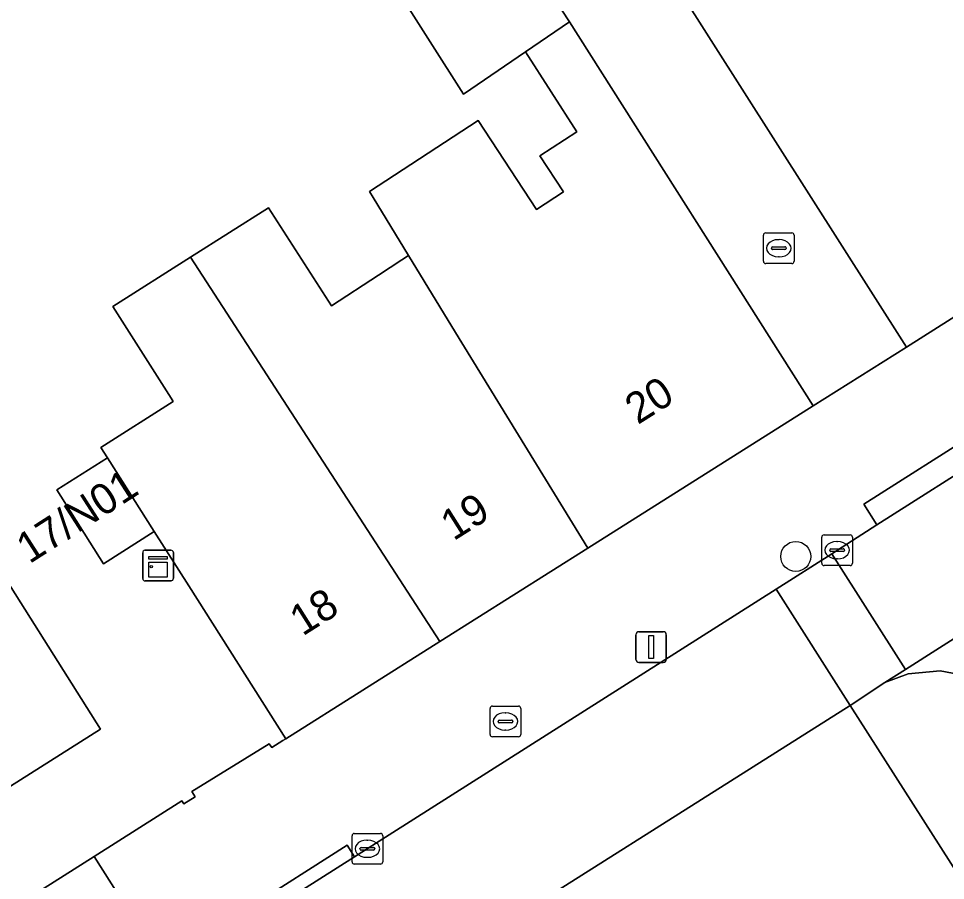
# Model space of a CAD drawing. Extents: x 160663 to 161506, y 382245 to 383291.
# Drawn here: x 160785.26 to 160815.49, y 383191.57 to 383219.69 of the extents above; entities that cross this region are included whole.
import ezdxf

# ---------------------------------------------------------------- set-up
doc = ezdxf.new("R2010")
doc.units = 0
for name, color, linetype in [('IMGEO_Boom', 7, 'Continuous'), ('IMGEO_Erf', 7, 'Continuous'), ('IMGEO_Kast', 7, 'Continuous'), ('IMGEO_Kolk', 7, 'Continuous'), ('IMGEO_Lichtmast', 7, 'Continuous'), ('IMGEO_Pand', 7, 'Continuous'), ('IMGEO_Pand_nummerreeks', 7, 'Continuous'), ('IMGEO_Parkeervlak_gesloten', 7, 'Continuous'), ('IMGEO_Parkeervlak_open', 7, 'Continuous'), ('IMGEO_Rijbaan_lokaal_gesloten', 7, 'Continuous'), ('IMGEO_Rijbaan_lokaal_open', 7, 'Continuous'), ('IMGEO_Rioolput', 7, 'Continuous'), ('IMGEO_Voetgangersgebied_open', 7, 'Continuous'), ('IMGEO_Voetpad_open', 7, 'Continuous')]:
    doc.layers.add(name, color=color, linetype=linetype)

msp = doc.modelspace()

# ---------------------------------------------------------------- linework, layer by layer
at = {"layer": 'IMGEO_Boom'}
msp.add_circle((160810.605, 383202.143), 0.489, dxfattribs=at)
at = {"layer": 'IMGEO_Erf'}
for points in [[(160799.08, 383225.923), (160803.23, 383219.586), (160811.173, 383207.059), (160814.215, 383208.968), (160806.764, 383220.698)], [(160790.812, 383201.181), (160789.687, 383202.954), (160788.036, 383201.906), (160786.509, 383204.312), (160788.159, 383205.36), (160787.946, 383205.695), (160790.307, 383207.2), (160790.242, 383207.302), (160788.34, 383210.3), (160790.873, 383211.908), (160793.413, 383213.52), (160795.464, 383210.321), (160796.995, 383211.321), (160797.758, 383211.82), (160797.977, 383211.963), (160796.829, 383213.85), (160796.707, 383214.052), (160800.251, 383216.368), (160802.147, 383213.465), (160803.027, 383214.04), (160802.265, 383215.208), (160803.466, 383215.992), (160801.794, 383218.605), (160799.769, 383217.222), (160795.199, 383224.421)], [(160781.782, 383206.257), (160787.928, 383196.514), (160781.611, 383192.511)], [(160772.211, 383182.539), (160787.728, 383192.359), (160790.588, 383194.169), (160790.653, 383194.068), (160791.019, 383194.303), (160790.91, 383194.473), (160793.433, 383196.036), (160793.515, 383195.909), (160793.875, 383196.14), (160793.972, 383196.198), (160790.812, 383201.181)]]:
    msp.add_lwpolyline(points, dxfattribs=at)
at = {"layer": 'IMGEO_Kast'}
for p, q in [((160789.309, 383201.422), (160789.309, 383202.263)), ((160789.309, 383202.263), (160789.309, 383201.422)), ((160789.384, 383202.347), (160790.225, 383202.347)), ((160790.225, 383202.347), (160789.384, 383202.347)), ((160790.309, 383202.272), (160790.309, 383201.431)), ((160790.309, 383201.431), (160790.309, 383202.272)), ((160790.234, 383201.347), (160789.393, 383201.347)), ((160789.393, 383201.347), (160790.234, 383201.347))]:
    msp.add_line(p, q, dxfattribs=at)
for points in [[(160789.504, 383202.137), (160790.104, 383202.137), (160790.104, 383202.052), (160789.504, 383202.052), (160789.504, 383202.137)], [(160789.504, 383201.962), (160790.104, 383201.962), (160790.104, 383201.473), (160789.504, 383201.473), (160789.504, 383201.962)]]:
    msp.add_lwpolyline(points, dxfattribs=at)
msp.add_circle((160789.588, 383201.811), 0.0377, dxfattribs=at)
for centre, start, end in [((160789.387, 383202.269), 92.4484, 184.2845), ((160789.387, 383202.269), 92.4484, 184.2845), ((160790.231, 383202.269), 2.4484, 94.2845), ((160790.231, 383202.269), 2.4484, 94.2845), ((160789.387, 383201.425), 182.4484, 274.2845), ((160789.387, 383201.425), 182.4484, 274.2845), ((160790.231, 383201.425), 272.4484, 4.2845), ((160790.231, 383201.425), 272.4484, 4.2845)]:
    msp.add_arc(centre, 0.0779, start, end, dxfattribs=at)
at = {"layer": 'IMGEO_Kolk'}
for p, q in [((160809.627, 383212.698), (160810.479, 383212.698)), ((160809.552, 383211.772), (160809.552, 383212.624)), ((160810.04, 383212.478), (160810.065, 383212.478)), ((160810.553, 383212.624), (160810.553, 383211.772)), ((160809.811, 383212.192), (160809.811, 383212.204)), ((160810.249, 383212.155), (160809.851, 383212.155)), ((160809.854, 383212.241), (160810.252, 383212.241)), ((160810.295, 383212.204), (160810.295, 383212.192)), ((160810.063, 383211.918), (160810.038, 383211.918)), ((160810.479, 383211.698), (160809.627, 383211.698)), ((160811.453, 383201.921), (160811.453, 383202.773)), ((160811.528, 383202.847), (160812.38, 383202.847)), ((160812.454, 383202.773), (160812.454, 383201.921)), ((160811.755, 383202.39), (160812.153, 383202.39)), ((160811.941, 383202.627), (160811.966, 383202.627)), ((160811.712, 383202.341), (160811.712, 383202.353)), ((160812.15, 383202.304), (160811.752, 383202.304)), ((160811.964, 383202.067), (160811.939, 383202.067)), ((160812.196, 383202.353), (160812.196, 383202.341)), ((160812.38, 383201.847), (160811.528, 383201.847)), ((160796.135, 383192.182), (160796.135, 383193.034)), ((160796.21, 383193.108), (160797.062, 383193.108)), ((160797.136, 383193.034), (160797.136, 383192.182)), ((160796.623, 383192.888), (160796.648, 383192.888)), ((160796.394, 383192.602), (160796.394, 383192.614)), ((160796.832, 383192.565), (160796.434, 383192.565)), ((160796.437, 383192.651), (160796.835, 383192.651)), ((160796.878, 383192.614), (160796.878, 383192.602)), ((160797.062, 383192.108), (160796.21, 383192.108)), ((160796.646, 383192.328), (160796.621, 383192.328))]:
    msp.add_line(p, q, dxfattribs=at)
for points in [[(160809.627, 383212.698), (160810.479, 383212.698)], [(160809.552, 383211.772), (160809.552, 383212.624)], [(160810.553, 383212.624), (160810.553, 383211.772)], [(160810.479, 383211.698), (160809.627, 383211.698)], [(160811.453, 383201.921), (160811.453, 383202.773)], [(160811.528, 383202.847), (160812.38, 383202.847)], [(160812.454, 383202.773), (160812.454, 383201.921)], [(160812.38, 383201.847), (160811.528, 383201.847)], [(160796.135, 383192.182), (160796.135, 383193.034)], [(160796.21, 383193.108), (160797.062, 383193.108)], [(160797.136, 383193.034), (160797.136, 383192.182)], [(160797.062, 383192.108), (160796.21, 383192.108)]]:
    msp.add_lwpolyline(points, dxfattribs=at)
for centre, radius, start, end in [((160809.629, 383212.622), 0.0765, 91.552, 178.448), ((160809.629, 383212.622), 0.0765, 91.552, 178.448), ((160810.477, 383212.622), 0.0765, 1.552, 88.448), ((160810.477, 383212.622), 0.0765, 1.552, 88.448), ((160809.851, 383212.201), 0.0403, 85.8775, 175.7526), ((160809.848, 383212.191), 0.0366, 178.938, 274.7102), ((160810.252, 383212.198), 0.043, 264.8664, 352.4533), ((160810.256, 383212.203), 0.0386, 1.7309, 96.639), ((160809.629, 383211.774), 0.0765, 181.552, 268.448), ((160809.629, 383211.774), 0.0765, 181.552, 268.448), ((160810.477, 383211.774), 0.0765, 271.552, 358.448), ((160810.477, 383211.774), 0.0765, 271.552, 358.448), ((160811.53, 383202.771), 0.0765, 91.552, 178.448), ((160811.53, 383202.771), 0.0765, 91.552, 178.448), ((160812.378, 383202.771), 0.0765, 1.552, 88.448), ((160812.378, 383202.771), 0.0765, 1.552, 88.448), ((160811.752, 383202.35), 0.0403, 85.8775, 175.7526), ((160812.157, 383202.352), 0.0386, 1.7309, 96.639), ((160811.749, 383202.34), 0.0366, 178.938, 274.7102), ((160812.153, 383202.347), 0.043, 264.8664, 352.4533), ((160811.53, 383201.923), 0.0765, 181.552, 268.448), ((160811.53, 383201.923), 0.0765, 181.552, 268.448), ((160812.378, 383201.923), 0.0765, 271.552, 358.448), ((160812.378, 383201.923), 0.0765, 271.552, 358.448), ((160796.212, 383193.032), 0.0765, 91.552, 178.448), ((160796.212, 383193.032), 0.0765, 91.552, 178.448), ((160797.06, 383193.032), 0.0765, 1.552, 88.448), ((160797.06, 383193.032), 0.0765, 1.552, 88.448), ((160796.434, 383192.611), 0.0403, 85.8775, 175.7526), ((160796.431, 383192.601), 0.0366, 178.938, 274.7102), ((160796.835, 383192.608), 0.043, 264.8664, 352.4533), ((160796.839, 383192.613), 0.0386, 1.7309, 96.639), ((160796.212, 383192.184), 0.0765, 181.552, 268.448), ((160796.212, 383192.184), 0.0765, 181.552, 268.448), ((160797.06, 383192.184), 0.0765, 271.552, 358.448), ((160797.06, 383192.184), 0.0765, 271.552, 358.448)]:
    msp.add_arc(centre, radius, start, end, dxfattribs=at)
for centre, major_axis, ratio, start_param, end_param in [((160810.039, 383212.198), (-0.387, 0.002), 0.722429, 4.712389, 7.853982), ((160810.064, 383212.198), (-0.39, 0.002), 0.717154, 1.570796, 4.712389), ((160811.94, 383202.347), (-0.387, 0.002), 0.722429, 4.712389, 7.853982), ((160811.965, 383202.347), (-0.39, 0.002), 0.717154, 1.570796, 4.712389), ((160796.622, 383192.608), (-0.387, 0.002), 0.722429, 4.712389, 7.853982), ((160796.647, 383192.608), (-0.39, 0.002), 0.717154, 1.570796, 4.712389)]:
    msp.add_ellipse(centre, major_axis=major_axis, ratio=ratio, start_param=start_param, end_param=end_param, dxfattribs=at)
at = {"layer": 'IMGEO_Lichtmast'}
for p, q in [((160805.493, 383199.687), (160806.283, 383199.687)), ((160806.283, 383199.687), (160805.493, 383199.687)), ((160805.393, 383198.787), (160805.393, 383199.587)), ((160805.393, 383199.587), (160805.393, 383198.787)), ((160806.383, 383199.587), (160806.383, 383198.787)), ((160806.383, 383198.787), (160806.383, 383199.587)), ((160806.283, 383198.687), (160805.493, 383198.687)), ((160805.493, 383198.687), (160806.283, 383198.687))]:
    msp.add_line(p, q, dxfattribs=at)
msp.add_lwpolyline([(160805.813, 383199.562), (160805.963, 383199.562), (160805.963, 383198.812), (160805.813, 383198.812), (160805.813, 383199.562)], dxfattribs=at)
for centre, start, end in [((160805.493, 383199.587), 90, 180), ((160805.493, 383199.587), 90, 180), ((160806.283, 383199.587), 0, 90), ((160806.283, 383199.587), 360, 90), ((160805.493, 383198.787), 180, 270), ((160805.493, 383198.787), 180, 270), ((160806.283, 383198.787), 270, 0), ((160806.283, 383198.787), 270, 0)]:
    msp.add_arc(centre, 0.1, start, end, dxfattribs=at)
at = {"layer": 'IMGEO_Pand'}
for points in [[(160825.512, 383216.14), (160819.403, 383225.863), (160818.107, 383227.903), (160806.764, 383220.698), (160814.215, 383208.968)], [(160799.08, 383225.923), (160795.199, 383224.421), (160799.769, 383217.222), (160801.794, 383218.605), (160803.23, 383219.586)], [(160803.23, 383219.586), (160801.794, 383218.605), (160803.466, 383215.992), (160802.265, 383215.208), (160803.027, 383214.04), (160802.147, 383213.465), (160800.251, 383216.368), (160796.707, 383214.052), (160796.829, 383213.85), (160797.977, 383211.963), (160799.505, 383209.451), (160803.822, 383202.417), (160811.173, 383207.059)], [(160799.505, 383209.451), (160797.977, 383211.963), (160797.758, 383211.82), (160796.995, 383211.321), (160795.464, 383210.321), (160793.413, 383213.52), (160790.873, 383211.908), (160799.001, 383199.374), (160803.822, 383202.417)], [(160789.687, 383202.954), (160790.812, 383201.181), (160793.972, 383196.198), (160799.001, 383199.374), (160790.873, 383211.908), (160788.34, 383210.3), (160790.242, 383207.302), (160790.307, 383207.2), (160787.946, 383205.695), (160788.159, 383205.36)], [(160789.687, 383202.954), (160788.159, 383205.36), (160786.509, 383204.312), (160788.036, 383201.906)]]:
    msp.add_lwpolyline(points, close=True, dxfattribs=at)
msp.add_lwpolyline([(160781.611, 383192.511), (160787.928, 383196.514), (160781.782, 383206.257)], dxfattribs=at)
at = {"layer": 'IMGEO_Parkeervlak_gesloten'}
msp.add_lwpolyline([(160867.459, 383233.842), (160866.622, 383232.757), (160865.378, 383231.474), (160864.441, 383230.558), (160863.852, 383230.131), (160814.182, 383198.457), (160813.512, 383198.029), (160814.275, 383198.311), (160815.313, 383198.409), (160816.291, 383198.226)], dxfattribs=at)
at = {"layer": 'IMGEO_Parkeervlak_open'}
msp.add_lwpolyline([(160800.785, 383187.545), (160811.908, 383170.165), (160817.688, 383174.203), (160824.203, 383178.755), (160812.384, 383197.277), (160798.038, 383188.212)], dxfattribs=at)
at = {"layer": 'IMGEO_Rijbaan_lokaal_gesloten'}
msp.add_lwpolyline([(160860.67, 383233.313), (160857.968, 383231.595), (160854.957, 383229.661), (160817.61, 383205.918), (160817.342, 383205.747), (160817.084, 383205.606), (160813.254, 383203.171), (160811.78, 383202.234), (160814.182, 383198.457), (160863.852, 383230.131)], dxfattribs=at)
msp.add_lwpolyline([(160809.966, 383201.081), (160796.215, 383192.339), (160792.947, 383190.262), (160795.551, 383186.201), (160796.863, 383187.404), (160798.038, 383188.212), (160812.384, 383197.277)], close=True, dxfattribs=at)
at = {"layer": 'IMGEO_Rijbaan_lokaal_open'}
msp.add_lwpolyline([(160813.512, 383198.029), (160814.182, 383198.457), (160811.78, 383202.234), (160809.966, 383201.081), (160812.384, 383197.277)], close=True, dxfattribs=at)
at = {"layer": 'IMGEO_Rioolput'}
for p, q in [((160800.712, 383197.261), (160801.564, 383197.261)), ((160800.637, 383196.335), (160800.637, 383197.187)), ((160801.125, 383197.041), (160801.15, 383197.041)), ((160801.638, 383197.187), (160801.638, 383196.335)), ((160800.896, 383196.755), (160800.896, 383196.767)), ((160801.334, 383196.718), (160800.936, 383196.718)), ((160800.939, 383196.804), (160801.337, 383196.804)), ((160801.38, 383196.767), (160801.38, 383196.755)), ((160801.148, 383196.481), (160801.123, 383196.481)), ((160801.564, 383196.261), (160800.712, 383196.261))]:
    msp.add_line(p, q, dxfattribs=at)
for points in [[(160800.712, 383197.261), (160801.564, 383197.261)], [(160800.637, 383196.335), (160800.637, 383197.187)], [(160801.638, 383197.187), (160801.638, 383196.335)], [(160801.564, 383196.261), (160800.712, 383196.261)]]:
    msp.add_lwpolyline(points, dxfattribs=at)
for centre, radius, start, end in [((160800.714, 383197.185), 0.0765, 91.552, 178.448), ((160800.714, 383197.185), 0.0765, 91.552, 178.448), ((160801.562, 383197.185), 0.0765, 1.552, 88.448), ((160801.562, 383197.185), 0.0765, 1.552, 88.448), ((160800.936, 383196.764), 0.0403, 85.8775, 175.7526), ((160800.933, 383196.754), 0.0366, 178.938, 274.7102), ((160801.337, 383196.761), 0.043, 264.8664, 352.4533), ((160801.341, 383196.766), 0.0386, 1.7309, 96.639), ((160800.714, 383196.337), 0.0765, 181.552, 268.448), ((160800.714, 383196.337), 0.0765, 181.552, 268.448), ((160801.562, 383196.337), 0.0765, 271.552, 358.448), ((160801.562, 383196.337), 0.0765, 271.552, 358.448)]:
    msp.add_arc(centre, radius, start, end, dxfattribs=at)
for centre, major_axis, ratio, start_param, end_param in [((160801.124, 383196.761), (-0.387, 0.002), 0.722429, 4.712389, 7.853982), ((160801.149, 383196.761), (-0.39, 0.002), 0.717154, 1.570796, 4.712389)]:
    msp.add_ellipse(centre, major_axis=major_axis, ratio=ratio, start_param=start_param, end_param=end_param, dxfattribs=at)
at = {"layer": 'IMGEO_Voetgangersgebied_open'}
msp.add_lwpolyline([(160816.291, 383198.226), (160815.313, 383198.409), (160814.275, 383198.311), (160813.512, 383198.029), (160812.384, 383197.277), (160824.203, 383178.755), (160825.075, 383177.569), (160826.976, 383178.905), (160831.12, 383181.818), (160850.335, 383195.323)], dxfattribs=at)
at = {"layer": 'IMGEO_Voetpad_open'}
for points in [[(160798.038, 383188.212), (160796.863, 383187.404), (160795.551, 383186.201), (160792.947, 383190.262), (160792.705, 383190.642), (160795.973, 383192.72), (160796.215, 383192.339), (160809.966, 383201.081), (160811.78, 383202.234), (160813.254, 383203.171), (160812.828, 383203.848), (160816.658, 383206.283), (160817.084, 383205.606), (160817.342, 383205.747), (160817.61, 383205.918), (160854.957, 383229.661), (160854.707, 383230.056), (160857.727, 383231.975), (160857.968, 383231.595), (160860.67, 383233.313)], [(160831.616, 383220.015), (160825.512, 383216.14), (160814.215, 383208.968), (160811.173, 383207.059), (160803.822, 383202.417), (160799.001, 383199.374), (160793.972, 383196.198), (160793.875, 383196.14), (160793.515, 383195.909), (160793.433, 383196.036), (160790.91, 383194.473), (160791.019, 383194.303), (160790.653, 383194.068), (160790.588, 383194.169), (160787.728, 383192.359), (160788.862, 383190.569), (160789.679, 383189.292), (160790.067, 383189.542), (160791.865, 383186.756), (160794.405, 383182.821), (160793.993, 383182.555), (160795.438, 383180.298)], [(160788.862, 383190.569), (160787.728, 383192.359), (160772.211, 383182.539), (160769.35, 383180.762), (160769.404, 383180.67), (160766.522, 383178.802), (160766.151, 383178.573), (160766.092, 383178.668), (160757.849, 383173.421), (160730.374, 383156.128), (160731.748, 383153.974), (160732.932, 383154.846)]]:
    msp.add_lwpolyline(points, dxfattribs=at)
for points in [[(160817.084, 383205.606), (160816.658, 383206.283), (160812.828, 383203.848), (160813.254, 383203.171)], [(160792.947, 383190.262), (160796.215, 383192.339), (160795.973, 383192.72), (160792.705, 383190.642)]]:
    msp.add_lwpolyline(points, close=True, dxfattribs=at)

# ---------------------------------------------------------------- texts
at = {"layer": 'IMGEO_Pand_nummerreeks'}
for s, rotation, p in [('20', 32.269, (160805.455, 383206.428)), ('17/N01', 32.6309, (160785.613, 383201.885)), ('19', 32.269, (160799.444, 383202.633)), ('18', 32.269, (160794.521, 383199.526))]:
    msp.add_text(s, height=1, rotation=rotation, dxfattribs=at).set_placement(p)

doc.saveas('drawing.dxf')
